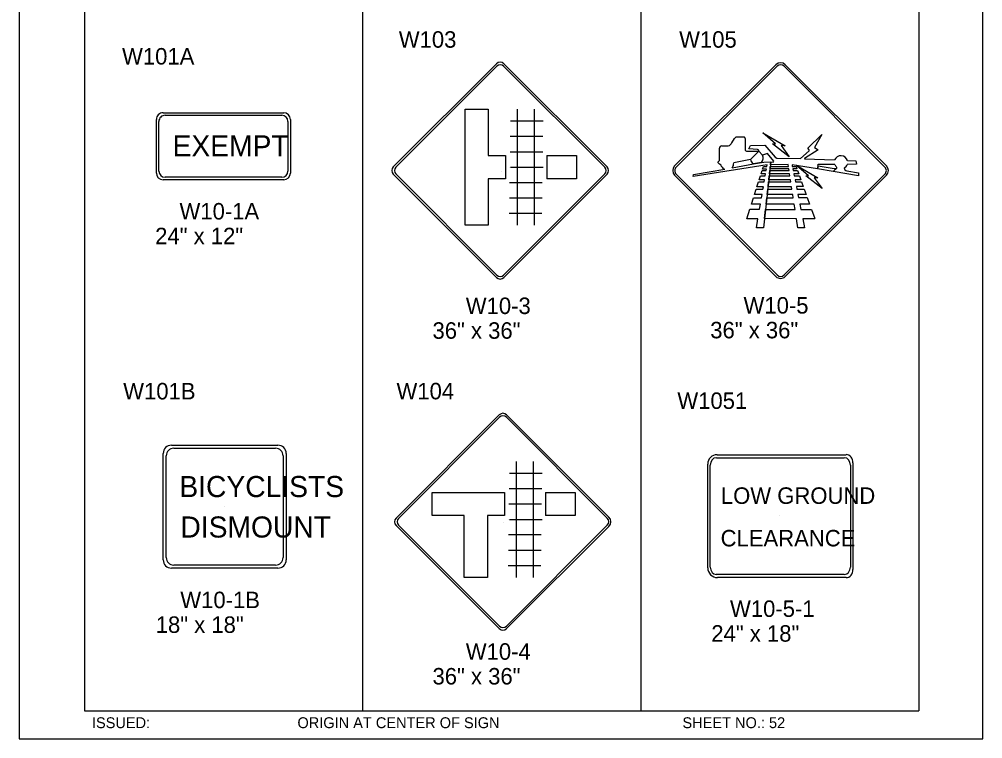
# Model space of a CAD drawing. Extents: x -5299 to 22597, y -19549 to -1808.
# Drawn here: x 2593 to 3294, y -5466 to -4942 of the extents above; entities that cross this region are included whole.
import ezdxf

# ---------------------------------------------------------------- set-up
doc = ezdxf.new("R2010")
doc.units = 0
for name, color, linetype in [('Level 1', 7, 'Continuous'), ('Level 2', 7, 'Continuous'), ('Level 3', 7, 'Continuous'), ('Level 62', 7, 'Continuous')]:
    doc.layers.add(name, color=color, linetype=linetype)

msp = doc.modelspace()

# ---------------------------------------------------------------- linework, layer by layer
at = {"layer": 'Level 1'}
for p, q in [((2640.66, -4645.77), (2640.66, -5445.77)), ((2842.99, -4645.77), (2842.99, -5445.77)), ((3045.33, -4645.77), (3045.33, -5445.77)), ((3247.67, -4645.77), (3247.67, -5445.77)), ((2865.31, -5049.8), (2940.42, -4974.69)), ((2867.1, -5050.02), (2940.64, -4976.48)), ((2945.56, -4976.48), (3019.11, -5050.02)), ((2945.79, -4974.69), (3020.9, -5049.8)), ((3070.01, -5049.09), (3143.7, -4975.4)), ((3071.17, -5049.94), (3144.55, -4976.56)), ((3149.64, -4976.56), (3223.01, -5049.94)), ((3150.49, -4975.4), (3224.18, -5049.09)), ((2917.56, -5092.18), (2917.56, -5007.77)), ((2917.56, -5007.77), (2934.42, -5007.77)), ((2934.42, -5007.77), (2934.42, -5041.59)), ((2955.44, -5007.77), (2955.44, -5092.18)), ((2967.91, -5007.77), (2967.91, -5092.18)), ((2950.55, -5016.28), (2974.31, -5016.28)), ((2950.55, -5016.28), (2950.55, -5016.28)), ((3134.09, -5025.01), (3150.38, -5034.42)), ((3143.43, -5032.95), (3134.09, -5025.01)), ((3166.91, -5036.13), (3177.11, -5026.17)), ((3177.11, -5026.17), (3171.74, -5035.74)), ((2950.39, -5027.53), (2974.16, -5027.53)), ((2950.39, -5027.53), (2950.39, -5027.53)), ((3111.7, -5032.16), (3113.47, -5029.2)), ((3113.47, -5029.2), (3114.67, -5027.87)), ((3114.67, -5027.87), (3120.51, -5027.87)), ((3121.45, -5029.07), (3121.45, -5037.59)), ((3153.45, -5042.44), (3141.3, -5032.95)), ((3141.3, -5032.95), (3143.43, -5032.95)), ((2742.74, -5034.79), (2742.74, -5034.79)), ((2950.24, -5038.77), (2974.01, -5038.77)), ((2950.24, -5038.77), (2950.24, -5038.77)), ((3102.56, -5045.17), (3102.56, -5036.26)), ((3104.29, -5034.53), (3109.06, -5034.53)), ((3122.24, -5038.35), (3131.4, -5038.35)), ((3124.11, -5036.68), (3125.2, -5034.19)), ((3130.19, -5037.22), (3124.11, -5036.68)), ((3131.4, -5038.35), (3125.16, -5044.4)), ((3125.16, -5044.4), (3131.4, -5038.35)), ((3125.2, -5034.19), (3135.72, -5033.95)), ((3131.2, -5037.69), (3130.19, -5037.22)), ((3131.4, -5038.35), (3131.2, -5037.69)), ((3137.51, -5040.03), (3134, -5041.33)), ((3135.72, -5033.95), (3143.12, -5042.59)), ((3142.11, -5045.55), (3137.51, -5040.03)), ((3150.38, -5034.42), (3147.44, -5034.29)), ((3147.44, -5034.29), (3153.45, -5042.44)), ((3161.66, -5043.69), (3167.92, -5038)), ((3174.38, -5037.3), (3164.57, -5043.61)), ((3167.92, -5037.46), (3166.91, -5036.13)), ((3167.92, -5038), (3167.92, -5037.46)), ((3171.74, -5035.74), (3174.38, -5037.3)), ((2934.42, -5041.59), (2946.89, -5041.59)), ((2946.89, -5041.59), (2946.89, -5058.46)), ((2977.05, -5041.59), (2998.69, -5041.59)), ((2977.05, -5041.59), (2977.05, -5058.46)), ((2998.69, -5041.59), (2998.69, -5058.46)), ((3101.72, -5045.99), (3102.56, -5045.17)), ((3101.72, -5046.8), (3101.72, -5045.99)), ((3102.72, -5047.83), (3101.72, -5046.8)), ((3111.93, -5050.36), (3127.3, -5047.53)), ((3125.16, -5044.4), (3112.98, -5046.88)), ((3133.32, -5046.5), (3127.3, -5047.53)), ((3127.3, -5047.53), (3133.32, -5046.52)), ((3133.32, -5046.52), (3134.97, -5046.24)), ((3140, -5046.22), (3134.62, -5094.15)), ((3134.97, -5046.24), (3140, -5046.22)), ((3139.78, -5048.18), (3140, -5046.22)), ((3140, -5046.22), (3141.72, -5046.25)), ((3141.72, -5046.25), (3142.11, -5045.55)), ((3143.12, -5042.59), (3144.44, -5043.37)), ((3144.44, -5043.37), (3161.66, -5043.69)), ((3164.57, -5043.61), (3164.41, -5044)), ((3164.41, -5044), (3186.36, -5044.7)), ((3195.86, -5045.24), (3201.78, -5045.32)), ((3201.78, -5045.32), (3202.33, -5047.89)), ((2944.31, -5053.02), (2944.31, -5053.02)), ((2950.09, -5050.02), (2950.09, -5050.02)), ((2950.55, -5050.03), (2974.31, -5050.03)), ((3137.29, -5048.19), (3083.54, -5056.88)), ((3083.67, -5055.29), (3106.42, -5051.43)), ((3103.76, -5048.63), (3102.72, -5047.83)), ((3104.16, -5049.45), (3103.76, -5048.63)), ((3132.88, -5054.89), (3133.64, -5052.49)), ((3133.64, -5052.49), (3136.57, -5052.49)), ((3134, -5051.36), (3134.62, -5049.43)), ((3136.77, -5051.33), (3134, -5051.36)), ((3134.62, -5049.43), (3137.09, -5049.42)), ((3136.57, -5052.49), (3136.77, -5051.33)), ((3137.09, -5049.42), (3137.29, -5048.19)), ((3139.03, -5054.88), (3139.29, -5052.5)), ((3139.29, -5052.5), (3153.28, -5052.53)), ((3139.43, -5051.32), (3139.63, -5049.47)), ((3153.1, -5051.32), (3139.43, -5051.32)), ((3139.63, -5049.47), (3152.81, -5049.48)), ((3152.61, -5048.15), (3139.78, -5048.18)), ((3152.81, -5049.48), (3152.61, -5048.15)), ((3153.28, -5052.53), (3153.1, -5051.32)), ((3173.9, -5051.24), (3155.42, -5048.2)), ((3155.42, -5048.2), (3155.65, -5049.39)), ((3155.65, -5049.39), (3158.33, -5049.4)), ((3159.01, -5051.31), (3156.03, -5051.3)), ((3156.03, -5051.3), (3156.26, -5052.43)), ((3156.26, -5052.43), (3159.42, -5052.44)), ((3158.33, -5049.4), (3159.01, -5051.31)), ((3167.36, -5056.26), (3158.58, -5048.72)), ((3158.58, -5048.72), (3159, -5048.79)), ((3159, -5048.79), (3174.27, -5057.76)), ((3159.42, -5052.44), (3160.3, -5054.9)), ((3174.38, -5049.07), (3173.9, -5051.24)), ((3173.9, -5051.24), (3174.38, -5049.07)), ((3185.27, -5053.18), (3173.9, -5051.24)), ((3174.38, -5049.07), (3186.04, -5050.93)), ((3186.67, -5048.05), (3174.44, -5047.97)), ((3185.27, -5053.18), (3187.92, -5050.69)), ((3187.66, -5050.93), (3185.27, -5053.18)), ((3203.73, -5056.38), (3185.27, -5053.18)), ((3186.04, -5050.93), (3187.66, -5050.93)), ((3188.15, -5050.23), (3187.84, -5049.91)), ((3187.92, -5050.69), (3188.15, -5050.23)), ((3195.32, -5052.56), (3203.73, -5054.04)), ((3202.33, -5047.89), (3195.55, -5047.97)), ((3203.73, -5054.04), (3203.73, -5056.38)), ((2940.42, -5130.28), (2865.31, -5055.16)), ((2940.64, -5128.49), (2867.1, -5054.94)), ((2934.42, -5058.46), (2934.42, -5092.18)), ((2946.89, -5058.46), (2934.42, -5058.46)), ((3019.11, -5054.94), (2945.56, -5128.49)), ((3020.9, -5055.16), (2945.79, -5130.28)), ((2973.7, -5061.27), (2949.94, -5061.27)), ((2949.94, -5061.27), (2949.94, -5061.27)), ((2998.69, -5058.46), (2977.05, -5058.46)), ((3143.7, -5129.57), (3070.01, -5055.88)), ((3144.55, -5128.4), (3071.17, -5055.03)), ((3083.54, -5056.88), (3083.67, -5055.29)), ((3129.91, -5064.19), (3131.01, -5060.74)), ((3131.01, -5060.74), (3135.18, -5060.74)), ((3131.49, -5059.24), (3132.45, -5056.22)), ((3135.44, -5059.24), (3131.49, -5059.24)), ((3132.45, -5056.22), (3135.94, -5056.22)), ((3136.17, -5054.89), (3132.88, -5054.89)), ((3135.18, -5060.74), (3135.44, -5059.24)), ((3135.94, -5056.22), (3136.17, -5054.89)), ((3137.98, -5064.2), (3138.37, -5060.71)), ((3138.37, -5060.71), (3154.55, -5060.76)), ((3138.54, -5059.24), (3138.86, -5056.37)), ((3154.3, -5059.16), (3138.54, -5059.24)), ((3138.86, -5056.37), (3153.88, -5056.38)), ((3153.65, -5054.88), (3139.03, -5054.88)), ((3146.75, -5054.64), (3146.75, -5054.64)), ((3223.01, -5055.03), (3149.64, -5128.4)), ((3224.18, -5055.88), (3150.49, -5129.57)), ((3153.88, -5056.38), (3153.65, -5054.88)), ((3154.55, -5060.76), (3154.3, -5059.16)), ((3160.3, -5054.9), (3156.75, -5054.9)), ((3156.75, -5054.9), (3157.03, -5056.3)), ((3157.03, -5056.3), (3160.81, -5056.3)), ((3161.85, -5059.19), (3157.6, -5059.19)), ((3157.6, -5059.19), (3157.91, -5060.74)), ((3157.91, -5060.74), (3162.4, -5060.74)), ((3160.81, -5056.3), (3161.85, -5059.19)), ((3162.4, -5060.74), (3163.63, -5064.17)), ((3165.54, -5056.34), (3167.36, -5056.26)), ((3177.29, -5065.59), (3165.54, -5056.34)), ((3174.27, -5057.76), (3171.5, -5057.71)), ((3171.5, -5057.71), (3177.29, -5065.59)), ((3128.13, -5069.79), (3129.31, -5066.07)), ((3129.31, -5066.07), (3134.29, -5066.07)), ((3134.6, -5064.2), (3129.91, -5064.19)), ((3134.29, -5066.07), (3134.6, -5064.2)), ((3137.35, -5069.78), (3137.77, -5066.07)), ((3137.77, -5066.07), (3155.37, -5066.06)), ((3155.08, -5064.18), (3137.98, -5064.2)), ((3155.37, -5066.06), (3155.08, -5064.18)), ((3163.63, -5064.17), (3158.59, -5064.17)), ((3158.59, -5064.17), (3158.98, -5066.1)), ((3158.98, -5066.1), (3164.33, -5066.1)), ((3164.33, -5066.1), (3165.65, -5069.77)), ((2973.55, -5072.52), (2949.78, -5072.52)), ((2949.78, -5072.52), (2949.78, -5072.52)), ((3125.85, -5076.93), (3127.34, -5072.26)), ((3127.34, -5072.26), (3133.25, -5072.26)), ((3133.66, -5069.79), (3128.13, -5069.79)), ((3133.25, -5072.26), (3133.66, -5069.79)), ((3136.55, -5076.91), (3137.08, -5072.24)), ((3137.08, -5072.24), (3156.31, -5072.2)), ((3155.94, -5069.79), (3137.35, -5069.78)), ((3156.31, -5072.2), (3155.94, -5069.79)), ((3165.65, -5069.77), (3159.71, -5069.77)), ((3159.71, -5069.77), (3160.17, -5072.1)), ((3160.17, -5072.1), (3166.48, -5072.08)), ((3166.48, -5072.08), (3168.21, -5076.89)), ((3122.44, -5087.64), (3124.67, -5080.62)), ((3124.67, -5080.62), (3131.84, -5080.63)), ((3132.46, -5076.92), (3125.85, -5076.93)), ((3131.84, -5080.63), (3132.46, -5076.92)), ((3135.37, -5087.45), (3136.12, -5080.73)), ((3136.12, -5080.73), (3157.62, -5080.73)), ((3157.02, -5076.83), (3136.55, -5076.91)), ((3157.62, -5080.73), (3157.02, -5076.83)), ((3168.21, -5076.89), (3161.12, -5076.89)), ((3161.12, -5076.89), (3161.89, -5080.73)), ((3161.89, -5080.73), (3169.59, -5080.73)), ((3169.59, -5080.73), (3171.99, -5087.4)), ((2973.4, -5083.77), (2949.63, -5083.77)), ((2949.63, -5083.77), (2949.63, -5083.77)), ((3130.66, -5087.61), (3122.44, -5087.64)), ((3129.56, -5094.15), (3130.66, -5087.61)), ((3158.68, -5087.57), (3135.37, -5087.45)), ((3159.68, -5094.08), (3158.68, -5087.57)), ((3172.03, -5087.52), (3163.24, -5087.52)), ((3163.24, -5087.52), (3164.54, -5094.08)), ((2934.42, -5092.18), (2917.56, -5092.18)), ((3134.62, -5094.15), (3129.56, -5094.15)), ((3164.54, -5094.08), (3159.68, -5094.08)), ((2867.31, -5305.36), (2942.43, -5230.25)), ((2869.1, -5305.59), (2942.65, -5232.04)), ((2947.57, -5232.04), (3021.03, -5305.5)), ((2947.79, -5230.25), (3022.19, -5304.65)), ((2703.87, -5252.36), (2781.4, -5252.36)), ((2705.61, -5254.6), (2779.66, -5254.6)), ((2697.91, -5335.86), (2697.91, -5258.33)), ((2700.14, -5334.12), (2700.14, -5260.07)), ((2785.13, -5260.07), (2785.13, -5334.12)), ((2787.37, -5258.33), (2787.37, -5335.86)), ((2954.68, -5264.12), (2954.68, -5348.53)), ((2967.15, -5264.12), (2967.15, -5348.53)), ((3100.37, -5261.47), (3193.48, -5261.47)), ((3100.87, -5259.23), (3194.9, -5259.23)), ((3094.07, -5341.52), (3094.07, -5266.03)), ((3095.89, -5341.02), (3095.89, -5266.94)), ((3197.95, -5266.94), (3197.95, -5341.02)), ((3199.78, -5265.19), (3199.78, -5342.76)), ((2949.78, -5272.62), (2973.55, -5272.62)), ((2949.78, -5272.62), (2949.78, -5272.62)), ((2949.63, -5283.87), (2973.4, -5283.87)), ((2949.63, -5283.87), (2949.63, -5283.87)), ((2893.47, -5303.56), (2893.47, -5286.69)), ((2893.47, -5286.69), (2946.28, -5286.69)), ((2946.28, -5286.69), (2946.28, -5303.56)), ((2975.99, -5286.69), (2997.62, -5286.69)), ((2975.99, -5286.69), (2975.99, -5303.55)), ((2997.62, -5286.69), (2997.62, -5303.55)), ((2742.46, -5296.98), (2742.46, -5296.98)), ((2949.48, -5295.12), (2973.24, -5295.12)), ((2949.48, -5295.12), (2949.48, -5295.12)), ((2916.95, -5303.56), (2893.47, -5303.56)), ((2916.95, -5348.53), (2916.95, -5303.56)), ((2933.81, -5303.56), (2933.81, -5348.53)), ((2946.28, -5303.56), (2933.81, -5303.56)), ((2949.33, -5306.37), (2949.33, -5306.37)), ((2949.78, -5306.37), (2973.55, -5306.37)), ((2997.62, -5303.55), (2975.99, -5303.55)), ((3146.27, -5303.4), (3146.27, -5303.4)), ((2942.43, -5385.84), (2867.31, -5310.73)), ((2942.65, -5384.05), (2869.1, -5310.51)), ((2945.35, -5308.35), (2945.35, -5308.35)), ((3021.03, -5310.59), (2947.57, -5384.05)), ((3022.19, -5311.44), (2947.79, -5385.84)), ((2972.94, -5317.62), (2949.18, -5317.62)), ((2949.18, -5317.62), (2949.18, -5317.62)), ((2972.79, -5328.87), (2949.02, -5328.87)), ((2949.02, -5328.87), (2949.02, -5328.87)), ((2781.4, -5341.83), (2703.87, -5341.83)), ((2779.66, -5339.59), (2705.61, -5339.59)), ((2972.64, -5340.11), (2948.87, -5340.11)), ((2948.87, -5340.11), (2948.87, -5340.11)), ((2933.81, -5348.53), (2916.95, -5348.53)), ((3193.48, -5346.48), (3100.32, -5346.48)), ((3194.9, -5348.72), (3101.27, -5348.72)), ((2640.66, -5445.77), (3247.67, -5445.77))]:
    msp.add_line(p, q, dxfattribs=at)
for centre, radius, start, end in [((2943.1, -4977.37), 3.79, 45, 135), ((2943.1, -4978.94), 3.48, 45, 135), ((3147.09, -4978.79), 4.8, 45.00038, 135.00019), ((3147.09, -4979.11), 3.6, 45.00019, 134.99961), ((3107.34, -5029.94), 4.89, 290.62308, 333.14019), ((3119.99, -5029.25), 1.47, 6.89483, 69.08358), ((3104.27, -5036.23), 1.71, 89.34089, 180.69044), ((3122.71, -5037.07), 1.36, 201.85522, 249.95985), ((3107.66, -5047.18), 5.33, 323.30229, 2.99663), ((3129.94, -5043.44), 4.87, 191.39432, 237.27267), ((3129.42, -5043.35), 5.01, 321.12024, 23.86766), ((3191.01, -5046.74), 5.08, 17.13108, 156.30377), ((2867.99, -5052.48), 3.79, 135, 225), ((2869.56, -5052.48), 3.48, 135, 225), ((3016.65, -5052.48), 3.48, 315, 45), ((3018.22, -5052.48), 3.79, 315, 45), ((3073.41, -5052.48), 4.8, 135.00019, 225), ((3073.72, -5052.48), 3.6, 134.99961, 225), ((3108.05, -5047.29), 4.45, 209.0259, 248.45842), ((3174.71, -5048.53), 0.627, 115.25862, 238.2154), ((3190.86, -5046.72), 4.4, 197.49891, 226.53207), ((3195.29, -5050.71), 1.85, 174.55521, 270.88617), ((3191.76, -5047.01), 3.91, 295.56248, 345.83648), ((3220.47, -5052.48), 3.6, 314.99981, 45.00019), ((3220.78, -5052.48), 4.8, 315.00038, 45.00038), ((2943.1, -5127.6), 3.79, 225, 315), ((2943.1, -5126.03), 3.48, 225, 315), ((3147.1, -5126.17), 4.8, 225, 315.00038), ((3147.09, -5125.86), 3.6, 225, 314.99981), ((2945.11, -5232.93), 3.79, 45, 135), ((2945.11, -5234.5), 3.48, 45, 135), ((2703.87, -5258.33), 5.96, 90, 180), ((2705.61, -5260.07), 5.47, 90, 180), ((2779.66, -5260.07), 5.47, 0, 90), ((2781.4, -5258.33), 5.96, 0, 90), ((3100.87, -5266.03), 6.8, 90, 180), ((2870, -5308.05), 3.79, 135, 225), ((2871.56, -5308.05), 3.48, 135, 225), ((3018.48, -5308.05), 3.6, 315, 44.99981), ((3018.8, -5308.05), 4.8, 315.00038, 45.00019), ((2705.61, -5334.12), 5.47, 180, 270), ((2779.66, -5334.12), 5.47, 270, 0), ((2703.87, -5335.86), 5.96, 180, 270), ((2781.4, -5335.86), 5.96, 270, 0), ((3101.27, -5341.52), 7.2, 180, 270), ((2945.11, -5383.16), 3.79, 225, 315), ((2945.11, -5381.59), 3.48, 225, 315)]:
    msp.add_arc(centre, radius, start, end, dxfattribs=at)
for centre, major_axis, start_param, end_param in [((3100.37, -5266.93), (0, 5.47), 0, 1.570796), ((3193.48, -5266.93), (0, 5.47), 4.712389, 6.283185), ((3194.9, -5265.19), (0, 5.97), 4.712389, 6.283185), ((3100.37, -5341.02), (0, -5.47), 4.712389, 6.283185), ((3193.48, -5341.02), (0, -5.47), 0, 1.570796), ((3194.9, -5342.76), (0, -5.97), 0, 1.570796)]:
    msp.add_ellipse(centre, major_axis=major_axis, ratio=0.817773, start_param=start_param, end_param=end_param, dxfattribs=at)
at = {"layer": 'Level 3'}
for p, q in [((2697.78, -5010.36), (2785.57, -5010.36)), ((2699.2, -5012.19), (2784.14, -5012.19)), ((2692.9, -5054.26), (2692.9, -5015.24)), ((2694.73, -5052.84), (2694.73, -5016.66)), ((2788.62, -5016.66), (2788.62, -5052.84)), ((2790.45, -5015.24), (2790.45, -5054.26)), ((3134, -5041.33), (3131.4, -5038.35)), ((2785.57, -5059.14), (2697.78, -5059.14)), ((2784.14, -5057.31), (2699.2, -5057.31))]:
    msp.add_line(p, q, dxfattribs=at)
for centre, major_axis, start_param, end_param in [((2697.78, -5015.24), (4.88, 0), 1.570796, 3.141593), ((2699.2, -5016.66), (4.47, 0), 1.570796, 3.141593), ((2784.15, -5016.66), (-4.47, 0), 3.141593, 4.712389), ((2785.57, -5015.24), (-4.88, 0), 3.141593, 4.712389), ((2697.78, -5054.26), (4.88, 0), 3.141593, 4.712389), ((2699.2, -5052.84), (4.47, 0), 3.141593, 4.712389), ((2784.15, -5052.84), (4.47, 0), 4.712389, 6.283185), ((2785.57, -5054.26), (4.88, 0), 4.712389, 6.283185)]:
    msp.add_ellipse(centre, major_axis=major_axis, ratio=0.999949, start_param=start_param, end_param=end_param, dxfattribs=at)
at = {"layer": 'Level 62'}
msp.add_lwpolyline([(2593.15, -5465.96), (3294.2, -5465.96), (3294.2, -4613.58), (2593.15, -4613.58)], close=True, dxfattribs=at)

# ---------------------------------------------------------------- texts
at = {"layer": 'Level 1'}
for s, height, p in [('EXEMPT', 15.363, (2704.68, -5042.15)), ('BICYCLISTS', 15.363, (2709.63, -5290.1)), ('LOW GROUND', 12, (3103.68, -5295.02)), ('DISMOUNT', 15.363, (2710.42, -5319.55)), ('CLEARANCE', 12, (3103.47, -5325.99))]:
    msp.add_text(s, height=height, dxfattribs=at).set_placement(p)
at = {"layer": 'Level 2'}
for s, p in [('W103', (2869.3, -4963.05)), ('W105', (3073.29, -4963.05)), ('W101A', (2667.93, -4975.29)), ('W101B', (2668.78, -5219.01)), ('W104', (2867.64, -5218.96)), ('W1051', (3072, -5225.93))]:
    msp.add_text(s, height=12, dxfattribs=at).set_placement(p)
at = {"layer": 'Level 3'}
for s, height, p in [('W10-1A', 12, (2709.75, -5088.07)), ('24" x 12"', 12, (2692.03, -5106.07)), ('W10-3', 12, (2918.06, -5156.87)), ('W10-5', 12, (3120.16, -5156.55)), ('36" x 36"', 12, (2893.83, -5174.87)), ('36" x 36"', 12, (3095.93, -5174.55)), ('W10-1B', 12, (2710.33, -5370.93)), ('W10-5-1', 12, (3110.31, -5377.31)), ('18" x 18"', 12, (2692.43, -5388.93)), ('24" x 18"', 12, (3096.7, -5395.31)), ('W10-4', 12, (2918.06, -5408.48)), ('36" x 36"', 12, (2893.83, -5426.48)), ('ISSUED:', 7.918, (2646.02, -5458.26)), ('ORIGIN AT CENTER OF SIGN', 7.9181, (2795.55, -5458.26)), ('SHEET NO.: 52', 7.918, (3075.71, -5458.26))]:
    msp.add_text(s, height=height, dxfattribs=at).set_placement(p)

doc.saveas('drawing.dxf')
